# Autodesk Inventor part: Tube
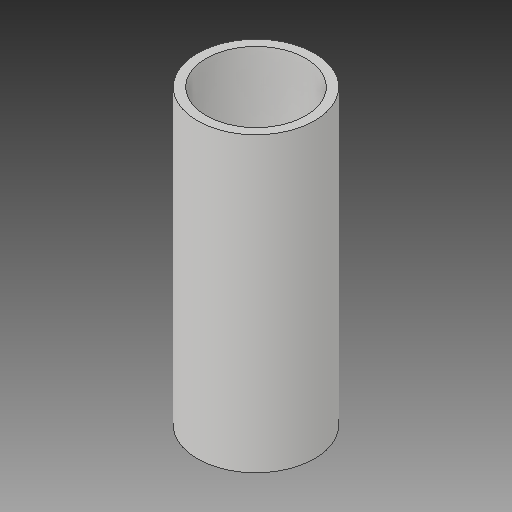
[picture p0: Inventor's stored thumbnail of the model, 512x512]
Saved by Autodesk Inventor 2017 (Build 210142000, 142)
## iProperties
Created: 2020-03
Part Number: Tube
Material: Generic
Document SubType Name: Modeling
Designer: user
Density: 1 g/cm^3
Appearance: Default
Author: user
Revision Number: ANY
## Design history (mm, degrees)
feature "Revolve1"
body "Solid1"
